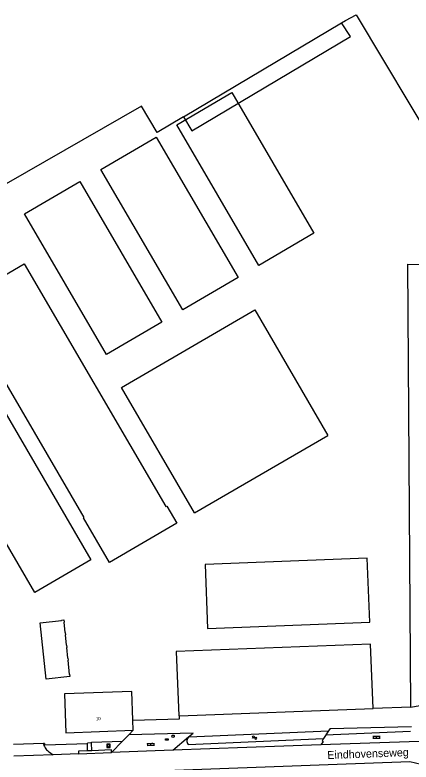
# Model space of a CAD drawing. Extents: x 135990 to 139000, y 393500 to 396000.
# Drawn here: x 137626.2 to 137750, y 395239.7 to 395473 of the extents above; entities that cross this region are included whole.
import ezdxf

# ---------------------------------------------------------------- set-up
doc = ezdxf.new("R2010")
doc.units = 0
for name, color, linetype in [('gg-afsc-haag', 7, 'Continuous'), ('gg-afsc-hekwerk', 7, 'Continuous'), ('gg-anno-huisnummerreeks BGT', 7, 'Continuous'), ('gg-anno-openbare ruimte label', 7, 'Continuous'), ('gg-bbg-bijgebouw', 7, 'Continuous'), ('gg-bbg-gedigitaliseerde bijgebouw', 7, 'Continuous'), ('gg-bbg-hoofdgebouw', 7, 'Continuous'), ('gg-knt-verharding', 7, 'Continuous'), ('gg-kntw-bovenkant insteek waterloop', 7, 'Continuous'), ('gg-kwrk-duiker nz buis', 7, 'Continuous'), ('gt-bbg-plantopografie pand', 7, 'Continuous'), ('gt-grn-groengrens', 7, 'Continuous'), ('gt-grn-vlakafsluiter', 7, 'Continuous'), ('gt-symb-brandkraan', 7, 'Continuous'), ('gt-symb-klinker verharding', 7, 'Continuous'), ('gt-symb-kolk center center', 7, 'Continuous'), ('gt-symb-rioolschacht', 7, 'Continuous'), ('gt-symb-watersymbool', 7, 'Continuous'), ('gx-grn-maaiveld', 7, 'Continuous')]:
    doc.layers.add(name, color=color, linetype=linetype)

# ---------------------------------------------------------------- blocks, each defined once
blk = doc.blocks.new('gt0-KL1')
at = {"layer": 'gt-symb-klinker verharding'}
for p, q in [((-1.15, 0.3), (1.15, 0.3)), ((-1, -0.3), (-1, 0.3)), ((-0.5, 0.3), (-0.5, 0.45)), ((0, -0.3), (0, 0.3)), ((0.5, 0.3), (0.5, 0.45)), ((1, -0.3), (1, 0.3)), ((-1.15, -0.3), (1.15, -0.3)), ((-0.5, -0.45), (-0.5, -0.3)), ((0.5, -0.45), (0.5, -0.3))]:
    blk.add_line(p, q, dxfattribs=at)
blk = doc.blocks.new('gt0-KOLKCC')
at = {"layer": 'gt-symb-kolk center center'}
blk.add_lwpolyline([(-0.38, 0.2), (0.38, 0.2), (0.38, -0.2), (-0.38, -0.2)], close=True, dxfattribs=at)
blk = doc.blocks.new('gt0-WA')
at = {"layer": 'gt-symb-watersymbool'}
for centre, start, end in [((-0.32, 0.02), 28.0725, 151.9275), ((0.43, 0.42), 208.0725, 331.9275), ((-0.32, -0.43), 28.0725, 151.9275), ((0.43, -0.03), 208.0725, 331.9275)]:
    blk.add_arc(centre, 0.425, start, end, dxfattribs=at)
blk = doc.blocks.new('gt0-BR')
at = {"layer": 'gt-symb-brandkraan'}
for centre, radius, start, end in [((-0.24, 0), 0.206, 107.5669, 252.4331), ((0.6, -2.66), 3, 106.892, 107.5669), ((0, -0.69), 0.938, 73.108, 106.892), ((-0.6, -2.66), 3, 72.4331, 73.108), ((0.24, 0), 0.206, 287.567, 72.4331), ((0.6, 2.66), 3, 252.4331, 253.108), ((0, 0.69), 0.938, 253.108, 286.8921), ((-0.6, 2.66), 3, 286.8921, 287.567)]:
    blk.add_arc(centre, radius, start, end, dxfattribs=at)
blk = doc.blocks.new('gt0-RS')
at = {"layer": 'gt-symb-rioolschacht'}
blk.add_lwpolyline([(-0.5, -0.5), (0.5, -0.5), (0.5, 0.5), (-0.5, 0.5)], close=True, dxfattribs=at)
blk.add_circle((0, 0), 0.375, dxfattribs=at)

msp = doc.modelspace()

# ---------------------------------------------------------------- linework, layer by layer
at = {"layer": 'gg-afsc-haag'}
msp.add_line((137650.163, 395245.826), (137659.874, 395246.183), dxfattribs=at)
at = {"layer": 'gg-afsc-hekwerk'}
for p, q in [((137749.899, 395256.834), (137738.132, 395256.384)), ((137749.899, 395256.834), (137738.132, 395256.384)), ((137635.128, 395245.448), (137625.77, 395245.111)), ((137635.5, 395245.461), (137635.128, 395245.448))]:
    msp.add_line(p, q, dxfattribs=at)
msp.add_lwpolyline([(137663.069, 395252.771), (137677.659, 395253.179), (137677.625, 395254.068)], dxfattribs=at)
msp.add_lwpolyline([(137663.069, 395252.771), (137677.659, 395253.179), (137677.625, 395254.068)], dxfattribs=at)
at = {"layer": 'gg-bbg-bijgebouw'}
msp.add_line((137677.625, 395254.068), (137738.132, 395256.384), dxfattribs=at)
for points in [[(137608.567, 395383.341), (137629.075, 395395.295), (137673.413, 395319.466), (137673.672, 395319.617), (137676.8, 395314.264), (137655.779, 395301.979), (137647.643, 395315.904), (137647.885, 395316.045), (137608.567, 395383.341)], [(137649.984, 395302.822), (137632.466, 395292.625), (137586.883, 395370.664), (137604.386, 395380.887), (137649.984, 395302.822)], [(137685.62, 395301.394), (137686.379, 395281.387), (137737.087, 395283.334), (137736.328, 395303.341), (137685.62, 395301.394)], [(137634.064, 395283.152), (137640.814, 395283.845), (137640.799, 395283.994), (137641.502, 395284.066), (137641.587, 395283.368), (137641.478, 395283.355), (137641.849, 395280.09), (137641.933, 395280.09), (137641.997, 395279.388), (137641.887, 395279.378), (137642.253, 395276.131), (137642.355, 395276.133), (137642.405, 395275.433), (137642.295, 395275.425), (137642.662, 395272.157), (137642.767, 395272.157), (137642.828, 395271.45), (137642.721, 395271.448), (137643.192, 395267.06), (137643.302, 395267.07), (137643.367, 395266.376), (137635.937, 395265.602), (137634.064, 395283.152)], [(137738.132, 395256.384), (137737.352, 395276.53), (137676.637, 395274.206), (137677.417, 395254.06), (137677.625, 395254.068)]]:
    msp.add_lwpolyline(points, dxfattribs=at)
at = {"layer": 'gg-bbg-gedigitaliseerde bijgebouw'}
msp.add_line((137682.313, 395317.46), (137724.01, 395341.627), dxfattribs=at)
for points in [[(137678.709, 395380.918), (137653.065, 395424.787), (137670.309, 395434.867)], [(137670.309, 395434.867), (137695.953, 395390.999), (137678.709, 395380.918)], [(137654.884, 395366.991), (137629.24, 395410.86), (137646.484, 395420.94)], [(137646.484, 395420.94), (137672.128, 395377.072), (137654.884, 395366.991)], [(137682.313, 395317.46), (137659.573, 395356.695), (137701.231, 395380.929), (137724.01, 395341.627)]]:
    msp.add_lwpolyline(points, dxfattribs=at)
at = {"layer": 'gg-bbg-hoofdgebouw'}
for p, q in [((137663.188, 395249.655), (137663.069, 395252.771)), ((137642.124, 395248.835), (137663.188, 395249.655))]:
    msp.add_line(p, q, dxfattribs=at)
msp.add_lwpolyline([(137663.069, 395252.771), (137662.726, 395261.73), (137641.664, 395260.926), (137642.124, 395248.835)], dxfattribs=at)
at = {"layer": 'gg-knt-verharding'}
for p, q in [((137724.678, 395250.19), (137724.179, 395249.405)), ((137661.785, 395248.193), (137659.874, 395246.183)), ((137724.179, 395249.405), (137722.637, 395246.981)), ((137635.128, 395245.448), (137635.173, 395245.211)), ((137648.86, 395245.457), (137648.856, 395245.577)), ((137648.943, 395243.124), (137648.86, 395245.457)), ((137650.168, 395245.616), (137650.163, 395245.826)), ((137650.229, 395243.166), (137650.168, 395245.616)), ((137656.362, 395242.658), (137659.874, 395246.183)), ((137675.534, 395243.362), (137680.458, 395247.516)), ((137755.977, 395246.191), (137721.795, 395245.014)), ((137650.229, 395243.166), (137648.943, 395243.124)), ((137675.534, 395243.362), (137656.362, 395242.658)), ((137721.795, 395245.014), (137675.534, 395243.362)), ((137638.187, 395241.934), (137625.852, 395241.464)), ((137637, 395242.709), (137638.187, 395241.934)), ((137646.107, 395242.236), (137638.187, 395241.934)), ((137646.107, 395242.236), (137656.362, 395242.658))]:
    msp.add_line(p, q, dxfattribs=at)
for points in [[(137680.458, 395247.516), (137681.884, 395248.719), (137661.785, 395248.193)], [(137722.637, 395246.981), (137722.219, 395246.324), (137722.52, 395246.12), (137721.795, 395245.014)], [(137648.943, 395243.124), (137646.097, 395243.083), (137646.107, 395242.236)], [(137656.362, 395242.658), (137656.36, 395243.469), (137650.229, 395243.166)], [(137670.595, 395236.879), (137724.06, 395238.932), (137749.611, 395239.866), (137753.154, 395239.028)]]:
    msp.add_lwpolyline(points, dxfattribs=at)
for centre, radius, start, end in [((137638.447, 395245.966), 3.36, 192.98531, 219.78279), ((137640.551, 395247.485), 5.952, 218.06142, 233.36962)]:
    msp.add_arc(centre, radius, start, end, dxfattribs=at)
at = {"layer": 'gg-kntw-bovenkant insteek waterloop'}
for p, q in [((137680.64, 395247.516), (137724.179, 395249.405)), ((137680.394, 395245.192), (137722.637, 395246.981))]:
    msp.add_line(p, q, dxfattribs=at)
msp.add_arc((137681.335, 395246.267), 1.429, 119.10367, 228.81159, dxfattribs=at)
at = {"layer": 'gg-kwrk-duiker nz buis'}
msp.add_line((137723.256, 395248.174), (137749.872, 395249.272), dxfattribs=at)
at = {"layer": 'gt-bbg-plantopografie pand'}
for points in [[(137702.428, 395394.784), (137676.784, 395438.652), (137694.028, 395448.733)], [(137694.028, 395448.733), (137719.672, 395404.865), (137702.428, 395394.784)]]:
    msp.add_lwpolyline(points, dxfattribs=at)
at = {"layer": 'gt-grn-groengrens'}
for p, q in [((137749.899, 395256.834), (137768.45, 395260.232)), ((137724.678, 395250.19), (137750.133, 395250.723)), ((137661.785, 395248.193), (137663.188, 395249.655))]:
    msp.add_line(p, q, dxfattribs=at)
for points in [[(137749.899, 395256.834), (137748.951, 395395.146), (137769.537, 395395.104)], [(137635.5, 395245.461), (137635.522, 395245.053), (137648.86, 395245.457)]]:
    msp.add_lwpolyline(points, dxfattribs=at)
at = {"layer": 'gt-grn-vlakafsluiter'}
for p, q in [((137650.168, 395245.616), (137648.856, 395245.577)), ((137680.64, 395247.516), (137680.458, 395247.516))]:
    msp.add_line(p, q, dxfattribs=at)
at = {"layer": 'gx-grn-maaiveld'}
msp.add_line((137678.845, 395441.161), (137728.312, 395470.517), dxfattribs=at)
for points in [[(137728.312, 395470.517), (137729.528, 395471.239), (137732.901, 395473.008), (137758.127, 395430.823), (137764.953, 395424.314), (137772.732, 395416.853), (137781.01, 395409.687)], [(137678.845, 395441.161), (137681.488, 395436.824), (137731.097, 395466.273), (137728.312, 395470.517)], [(137678.845, 395441.161), (137670.673, 395436.311), (137665.818, 395444.491), (137623.533, 395420.267), (137618.074, 395417.139)]]:
    msp.add_lwpolyline(points, dxfattribs=at)

# ---------------------------------------------------------------- block references
at = {"layer": 'gt-symb-brandkraan', "rotation": -178.49893256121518}
msp.add_blockref('gt0-BR', (137675.644, 395247.72), dxfattribs=at)
at = {"layer": 'gt-symb-klinker verharding', "rotation": 1.4908448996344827}
for p in [(137739.237, 395247.431), (137668.701, 395245.174)]:
    msp.add_blockref('gt0-KL1', p, dxfattribs=at)
at = {"layer": 'gt-symb-kolk center center', "rotation": 2.1783688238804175}
msp.add_blockref('gt0-KOLKCC', (137673.682, 395246.728), dxfattribs=at)
at = {"layer": 'gt-symb-rioolschacht'}
msp.add_blockref('gt0-RS', (137655.484, 395244.735), dxfattribs=at)
at = {"layer": 'gt-symb-watersymbool', "rotation": 0.973934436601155}
msp.add_blockref('gt0-WA', (137701.042, 395247.281), dxfattribs=at)

# ---------------------------------------------------------------- texts
at = {"layer": 'gg-anno-huisnummerreeks BGT'}
msp.add_text('10', height=1, rotation=2.2, dxfattribs=at).set_placement((137651.509, 395252.703))
at = {"layer": 'gg-anno-openbare ruimte label'}
msp.add_text('Eindhovenseweg', height=2.5, rotation=2.1, dxfattribs=at).set_placement((137723.878, 395240.586))

doc.saveas('drawing.dxf')
